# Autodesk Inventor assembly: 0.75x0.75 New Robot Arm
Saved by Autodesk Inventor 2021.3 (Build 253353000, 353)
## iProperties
Created: 2022-04
Part Number: 0.75x0.75 New Robot Arm
Document SubType Name: Assembly
Designer: Administrator
Title: 0.75x0.75 New Robot Arm v27
Author: Administrator
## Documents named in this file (2)
- c:\worker\convert-fusion-r02\tmp\job-1\1947\output\files\b646c1d8-b244-4b99-aa07-785a453b8ac0\b02acdbe-10f1-4be6-8153-73a1f03033d5.iam
- c:\worker\convert-fusion-r02\tmp\job-1\1947\output\files\b646c1d8-b244-4b99-aa07-785a453b8ac0\Component1.ipt
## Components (1 placed, 1 different names)
1. Component1:1
